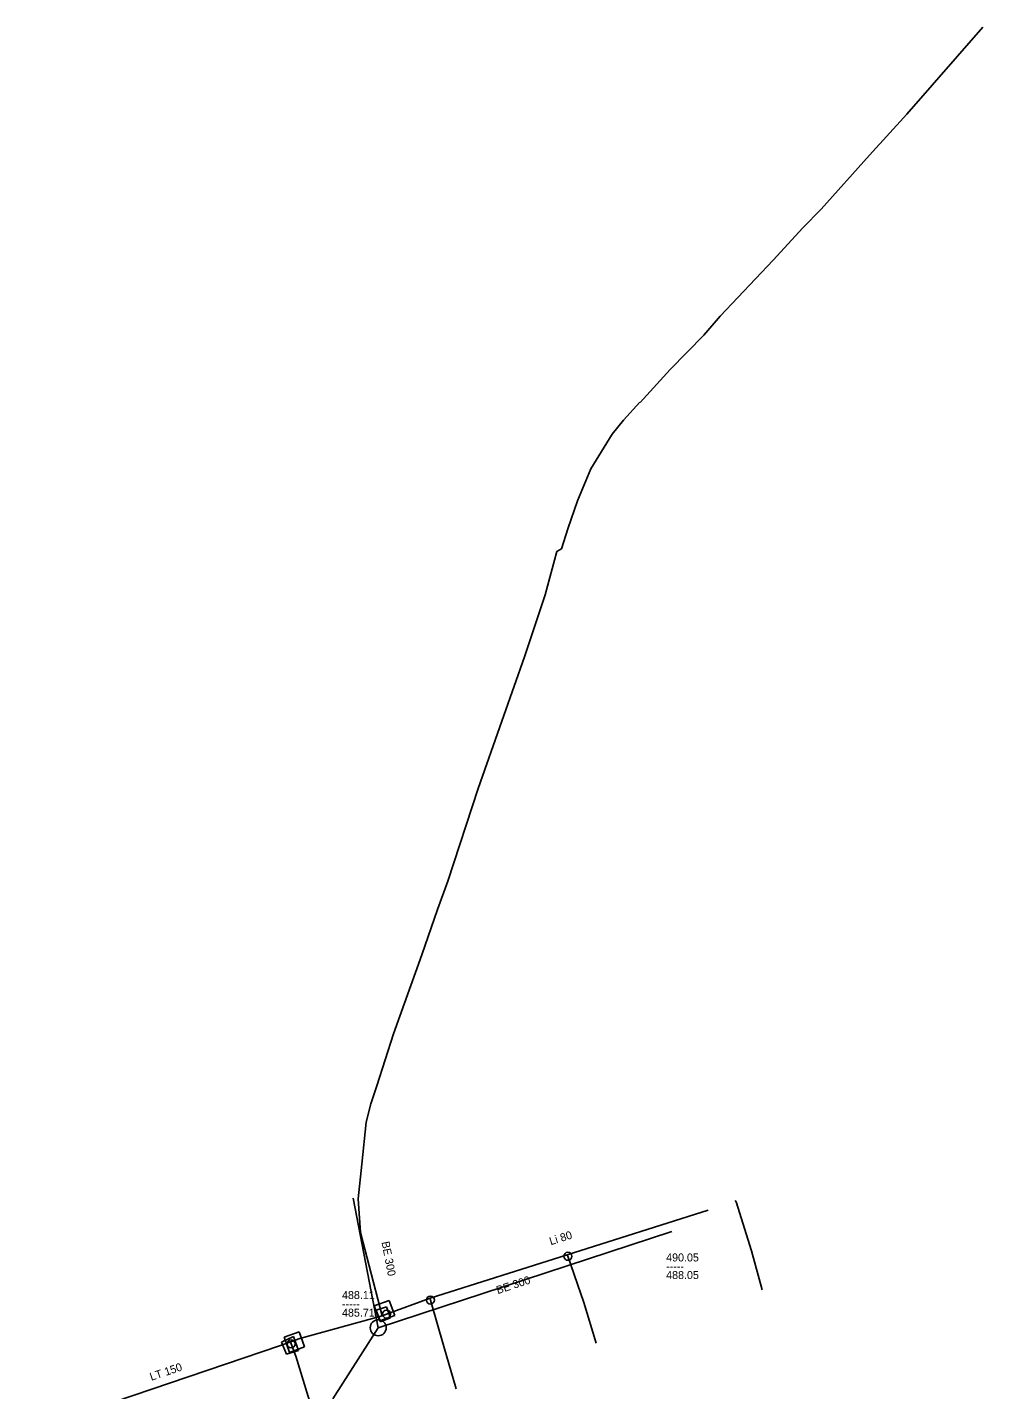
# Model space of a CAD drawing. Extents: x -685576 to -685179, y -1163336 to -1162895.
# Drawn here: x -685453.5 to -685334.1, y -1163065.1 to -1162894.9 of the extents above; entities that cross this region are included whole.
import ezdxf

# ---------------------------------------------------------------- set-up
doc = ezdxf.new("R2010")
doc.units = 0
doc.layers.add('Level 0', color=7, linetype='Continuous')

msp = doc.modelspace()

# ---------------------------------------------------------------- linework, layer by layer
at = {"layer": 'Level 0'}
for p, q in [((-685334.12, -1162894.92), (-685343.6, -1162905.78)), ((-685343.6, -1162905.78), (-685348.26, -1162910.89)), ((-685348.26, -1162910.89), (-685354.31, -1162917.66)), ((-685354.31, -1162917.66), (-685356.59, -1162919.99)), ((-685356.59, -1162919.99), (-685360.29, -1162924.01)), ((-685360.29, -1162924.01), (-685366.91, -1162931.03)), ((-685366.91, -1162931.03), (-685368.95, -1162933.37)), ((-685368.95, -1162933.37), (-685373.17, -1162937.67)), ((-685373.17, -1162937.67), (-685376.93, -1162941.79)), ((-685376.97, -1162941.75), (-685379, -1162944)), ((-685376.93, -1162941.79), (-685376.97, -1162941.75)), ((-685379, -1162944), (-685380.4, -1162945.74)), ((-685380.4, -1162945.74), (-685383.06, -1162950.09)), ((-685383.06, -1162950.09), (-685384.76, -1162954.07)), ((-685384.76, -1162954.07), (-685385.96, -1162957.58)), ((-685385.96, -1162957.58), (-685386.73, -1162960.07)), ((-685387.32, -1162960.42), (-685388.78, -1162965.81)), ((-685386.73, -1162960.07), (-685387.32, -1162960.42)), ((-685388.78, -1162965.81), (-685391.35, -1162973.57)), ((-685391.35, -1162973.57), (-685393.95, -1162980.91)), ((-685394.19, -1162981.63), (-685397.14, -1162990.04)), ((-685393.95, -1162980.91), (-685394.19, -1162981.63)), ((-685397.14, -1162990.04), (-685400.94, -1163001.59)), ((-685400.94, -1163001.59), (-685402.22, -1163005.13)), ((-685402.22, -1163005.13), (-685404.17, -1163010.82)), ((-685404.17, -1163010.82), (-685407.71, -1163020.66)), ((-685407.71, -1163020.66), (-685409.8, -1163027.19)), ((-685409.8, -1163027.19), (-685410.57, -1163029.41)), ((-685410.57, -1163029.41), (-685411.13, -1163031.71)), ((-685411.13, -1163031.71), (-685411.68, -1163036.96)), ((-685411.68, -1163036.96), (-685412.16, -1163041.28)), ((-685412.75, -1163041.19), (-685409.64, -1163057.39)), ((-685412.16, -1163041.28), (-685411.87, -1163045.49)), ((-685365.05, -1163041.51), (-685364.92, -1163041.67)), ((-685364.92, -1163041.67), (-685363, -1163047.78)), ((-685386.05, -1163048.29), (-685368.43, -1163042.71)), ((-685411.87, -1163045.49), (-685409.16, -1163055.9)), ((-685372.95, -1163045.37), (-685409.64, -1163057.39)), ((-685403.16, -1163053.71), (-685386.05, -1163048.29)), ((-685386.05, -1163048.29), (-685385.95, -1163048.47)), ((-685385.95, -1163048.47), (-685383.94, -1163054.26)), ((-685363, -1163047.78), (-685361.68, -1163052.66)), ((-685408.25, -1163053.99), (-685410.13, -1163054.67)), ((-685410.13, -1163054.67), (-685409.45, -1163056.55)), ((-685408.59, -1163054.77), (-685409.9, -1163055.21)), ((-685409.9, -1163055.21), (-685409.36, -1163056.66)), ((-685408.6, -1163055.69), (-685403.16, -1163053.71)), ((-685408.09, -1163056.16), (-685408.59, -1163054.77)), ((-685407.57, -1163055.87), (-685408.25, -1163053.99)), ((-685403.16, -1163053.71), (-685403.11, -1163053.94)), ((-685403.11, -1163053.94), (-685401.43, -1163059.72)), ((-685383.94, -1163054.26), (-685382.41, -1163059.31)), ((-685409.16, -1163055.9), (-685419.45, -1163058.72)), ((-685409.45, -1163056.55), (-685407.57, -1163055.87)), ((-685409.36, -1163056.66), (-685408.09, -1163056.16)), ((-685409.16, -1163055.9), (-685408.6, -1163055.69)), ((-685420.23, -1163058.5), (-685421.7, -1163059.18)), ((-685419.52, -1163057.91), (-685421.4, -1163058.59)), ((-685421.4, -1163058.59), (-685420.72, -1163060.47)), ((-685419.45, -1163058.72), (-685420.6, -1163059.15)), ((-685419.58, -1163060.23), (-685420.23, -1163058.5)), ((-685418.84, -1163059.79), (-685419.52, -1163057.91)), ((-685409.64, -1163057.39), (-685415.3, -1163066.26)), ((-685453.48, -1163070.32), (-685421.84, -1163059.63)), ((-685420.6, -1163059.15), (-685421.84, -1163059.63)), ((-685421.7, -1163059.18), (-685421.08, -1163060.71)), ((-685421.08, -1163060.71), (-685419.58, -1163060.23)), ((-685420.72, -1163060.47), (-685418.84, -1163059.79)), ((-685420.6, -1163059.15), (-685420.52, -1163059.42)), ((-685420.52, -1163059.42), (-685419.92, -1163060.93)), ((-685401.43, -1163059.72), (-685399.89, -1163065.02)), ((-685419.92, -1163060.93), (-685400.96, -1163122.89))]:
    msp.add_line(p, q, dxfattribs=at)
for centre, radius in [((-685385.95, -1163048.47), 0.5), ((-685403.11, -1163053.94), 0.5), ((-685408.6, -1163055.69), 0.5), ((-685409.64, -1163057.39), 1), ((-685420.52, -1163059.42), 0.5)]:
    msp.add_circle(centre, radius, dxfattribs=at)

# ---------------------------------------------------------------- texts
for s, rotation, p in [('BE 300', 280.867, (-685409.23, -1163046.7)), ('Li 80', 17.572, (-685388.08, -1163047.09)), ('BE 300', 18.139, (-685394.7, -1163053.2)), ('LT 150', 18.668, (-685437.98, -1163064.03))]:
    msp.add_text(s, height=1, rotation=rotation, dxfattribs=at).set_placement(p)
for s, p in [('490.05', (-685373.67, -1163049.11)), ('-----', (-685373.67, -1163050.21)), ('488.05', (-685373.67, -1163051.31)), ('488.11', (-685414.16, -1163053.81)), ('485.71', (-685414.16, -1163056.01)), ('-----', (-685414.16, -1163054.91))]:
    msp.add_text(s, height=1, dxfattribs=at).set_placement(p)

doc.saveas('drawing.dxf')
